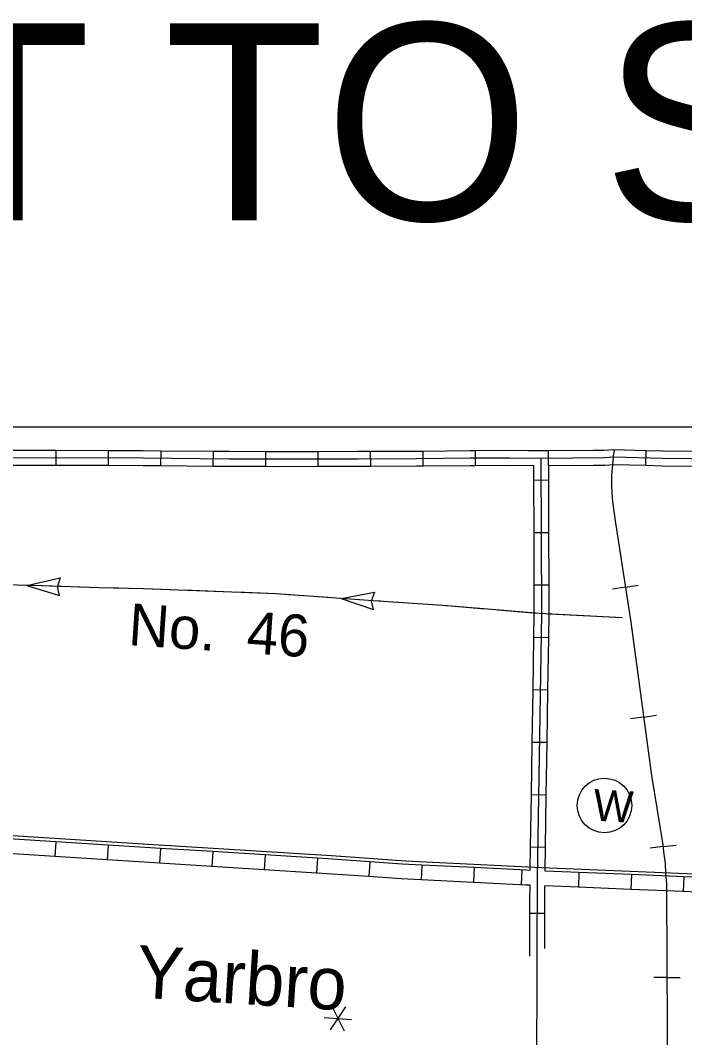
# Model space of a CAD drawing. Extents: x 1366406 to 1373462, y 376856 to 381998.
# Drawn here: x 1369100.9 to 1369209.2, y 380268.5 to 380434.5 of the extents above; entities that cross this region are included whole.
import ezdxf

# ---------------------------------------------------------------- set-up
doc = ezdxf.new("R2010")
doc.units = 0
for name, color, linetype in [('24', 7, 'Continuous'), ('32', 7, 'Continuous'), ('40', 7, 'Continuous'), ('43', 7, 'Continuous'), ('45', 7, 'Continuous'), ('48', 7, 'Continuous'), ('57', 7, 'Continuous'), ('Level 2', 7, 'Continuous'), ('R_No Plot', 7, 'Continuous')]:
    doc.layers.add(name, color=color, linetype=linetype)

msp = doc.modelspace()

# ---------------------------------------------------------------- linework, layer by layer
at = {"layer": '32'}
for p, q in [((1369106.69, 380361.9), (1369106.7, 380364.33)), ((1369115.24, 380361.87), (1369115.25, 380364.3)), ((1369123.79, 380361.83), (1369123.81, 380364.26)), ((1369132.34, 380361.75), (1369132.37, 380364.18)), ((1369140.9, 380361.71), (1369140.91, 380364.14)), ((1369149.46, 380361.71), (1369149.46, 380364.14)), ((1369158.02, 380361.73), (1369158.01, 380364.16)), ((1369166.58, 380361.77), (1369166.56, 380364.2)), ((1369175.13, 380361.86), (1369175.12, 380364.29)), ((1369187.06, 380359.43), (1369184.63, 380359.42)), ((1369187.09, 380350.87), (1369184.66, 380350.86)), ((1369187.13, 380342.32), (1369184.7, 380342.31)), ((1369187.08, 380333.74), (1369184.65, 380333.78)), ((1369186.94, 380325.19), (1369184.51, 380325.23)), ((1369186.8, 380316.64), (1369184.37, 380316.68)), ((1369186.66, 380308.08), (1369184.24, 380308.12)), ((1369106.64, 380300.47), (1369106.48, 380298.05)), ((1369115.17, 380299.93), (1369115.02, 380297.5)), ((1369123.71, 380299.39), (1369123.56, 380296.96)), ((1369132.24, 380298.85), (1369132.09, 380296.43)), ((1369186.53, 380299.53), (1369184.1, 380299.57)), ((1369140.78, 380298.32), (1369140.63, 380295.89)), ((1369149.32, 380297.78), (1369149.17, 380295.36)), ((1369157.86, 380297.2), (1369157.69, 380294.77)), ((1369166.37, 380296.67), (1369166.25, 380294.24)), ((1369174.92, 380296.25), (1369174.8, 380293.82)), ((1369182.68, 380295.86), (1369182.56, 380293.44)), ((1369191.99, 380295.46), (1369191.9, 380293.03)), ((1369200.54, 380295.11), (1369200.44, 380292.69)), ((1369209.09, 380294.76), (1369208.99, 380292.34)), ((1369186.42, 380288.76), (1369183.99, 380288.77))]:
    msp.add_line(p, q, dxfattribs=at)
for points in [[(1368944.66, 380365.32), (1368945.27, 380364.79), (1368945.98, 380364.3), (1368947.17, 380363.76), (1368948.17, 380363.56), (1368949.47, 380363.57), (1368950.6, 380363.56), (1368977.56, 380363.5), (1368994.49, 380363.45), (1369014.52, 380363.36), (1369057.49, 380363.5), (1369079.6, 380363.29), (1369099.69, 380363.13), (1369120.87, 380363.07), (1369134.89, 380362.95), (1369142.96, 380362.92), (1369155.95, 380362.94), (1369165.49, 380362.98), (1369174.24, 380363.07), (1369180.67, 380363.1), (1369185.83, 380363.06)], [(1369098.15, 380364.36), (1369099.7, 380364.35), (1369106.7, 380364.33)], [(1369106.7, 380364.33), (1369115.25, 380364.3)], [(1369115.25, 380364.3), (1369120.88, 380364.28), (1369123.81, 380364.26)], [(1369123.81, 380364.26), (1369132.37, 380364.18)], [(1369132.37, 380364.18), (1369134.9, 380364.16), (1369140.91, 380364.14)], [(1369140.91, 380364.14), (1369142.96, 380364.13), (1369149.46, 380364.14)], [(1369149.46, 380364.14), (1369155.94, 380364.16), (1369158.01, 380364.16)], [(1369158.01, 380364.16), (1369165.48, 380364.19), (1369166.56, 380364.2)], [(1369166.56, 380364.2), (1369174.23, 380364.28), (1369175.12, 380364.29)], [(1369175.12, 380364.29), (1369180.67, 380364.32), (1369183.68, 380364.29)], [(1369183.68, 380364.29), (1369187.04, 380364.27)], [(1369187.06, 380359.43), (1369187.04, 380364.27)], [(1369098.13, 380361.93), (1369099.69, 380361.92), (1369106.69, 380361.9)], [(1369106.69, 380361.9), (1369115.24, 380361.87)], [(1369115.24, 380361.87), (1369120.86, 380361.85), (1369123.79, 380361.83)], [(1369123.79, 380361.83), (1369132.34, 380361.75)], [(1369132.34, 380361.75), (1369134.88, 380361.73), (1369140.9, 380361.71)], [(1369158.02, 380361.73), (1369165.5, 380361.76), (1369166.58, 380361.77)], [(1369166.58, 380361.77), (1369174.25, 380361.85), (1369175.13, 380361.86)], [(1369175.13, 380361.86), (1369180.67, 380361.89), (1369184.62, 380361.86)], [(1369184.63, 380359.42), (1369184.62, 380361.86)], [(1369185.19, 380282.45), (1369185.23, 380294.52), (1369185.93, 380337.65), (1369185.83, 380363.06)], [(1369140.9, 380361.71), (1369142.96, 380361.7), (1369149.46, 380361.71)], [(1369149.46, 380361.71), (1369155.95, 380361.73), (1369158.02, 380361.73)], [(1369184.66, 380350.86), (1369184.63, 380359.42)], [(1369187.09, 380350.87), (1369187.06, 380359.43)], [(1369184.7, 380342.31), (1369184.66, 380350.86)], [(1369187.13, 380342.32), (1369187.09, 380350.87)], [(1369184.65, 380333.78), (1369184.71, 380337.66), (1369184.7, 380342.31)], [(1369187.08, 380333.74), (1369187.14, 380337.65), (1369187.13, 380342.32)], [(1369184.51, 380325.23), (1369184.65, 380333.78)], [(1369186.94, 380325.19), (1369187.08, 380333.74)], [(1369184.37, 380316.68), (1369184.51, 380325.23)], [(1369186.8, 380316.64), (1369186.94, 380325.19)], [(1369184.24, 380308.12), (1369184.37, 380316.68)], [(1369186.66, 380308.08), (1369186.8, 380316.64)], [(1369184.1, 380299.57), (1369184.24, 380308.12)], [(1369186.53, 380299.53), (1369186.66, 380308.08)], [(1369252.4, 380293.26), (1369251.01, 380293.38), (1369242.85, 380293.7), (1369229.28, 380294.44), (1369185.88, 380296.21), (1369163.73, 380297.31), (1369151.6, 380298.16), (1369120.91, 380300.08), (1369100.42, 380301.39), (1369085.32, 380302.07), (1369046.26, 380303.51), (1369036.14, 380303.8), (1369035.29, 380303.84)], [(1369106.64, 380300.47), (1369099.84, 380300.91), (1369098.08, 380300.99)], [(1369115.17, 380299.93), (1369106.64, 380300.47)], [(1369123.71, 380299.39), (1369120.34, 380299.6), (1369115.17, 380299.93)], [(1369132.24, 380298.85), (1369123.71, 380299.39)], [(1369140.78, 380298.32), (1369132.24, 380298.85)], [(1369184.04, 380295.8), (1369184.1, 380299.57)], [(1369186.46, 380295.69), (1369186.53, 380299.53)], [(1369106.48, 380298.05), (1369099.71, 380298.48), (1369097.97, 380298.56)], [(1369115.02, 380297.5), (1369106.48, 380298.05)], [(1369123.56, 380296.96), (1369120.18, 380297.18), (1369115.02, 380297.5)], [(1369149.32, 380297.78), (1369140.78, 380298.32)], [(1369157.86, 380297.2), (1369151.04, 380297.68), (1369149.32, 380297.78)], [(1369166.37, 380296.67), (1369163.15, 380296.83), (1369157.86, 380297.2)], [(1369132.09, 380296.43), (1369123.56, 380296.96)], [(1369140.63, 380295.89), (1369132.09, 380296.43)], [(1369149.17, 380295.36), (1369140.63, 380295.89)], [(1369174.92, 380296.25), (1369166.37, 380296.67)], [(1369183.46, 380295.83), (1369174.92, 380296.25)], [(1369184.04, 380295.8), (1369183.46, 380295.83)], [(1369191.99, 380295.46), (1369186.46, 380295.69)], [(1369200.54, 380295.11), (1369191.99, 380295.46)], [(1369157.69, 380294.77), (1369150.88, 380295.25), (1369149.17, 380295.36)], [(1369166.25, 380294.24), (1369163.01, 380294.4), (1369157.69, 380294.77)], [(1369174.8, 380293.82), (1369166.25, 380294.24)], [(1369183.34, 380293.4), (1369174.8, 380293.82)], [(1369209.09, 380294.76), (1369200.54, 380295.11)], [(1369217.63, 380294.42), (1369209.09, 380294.76)], [(1369184.01, 380293.37), (1369183.34, 380293.4)], [(1369184, 380291), (1369184.01, 380293.37)], [(1369186.43, 380290.99), (1369186.44, 380293.26)], [(1369191.9, 380293.03), (1369186.44, 380293.26)], [(1369200.44, 380292.69), (1369191.9, 380293.03)], [(1369208.99, 380292.34), (1369200.44, 380292.69)], [(1369217.53, 380291.99), (1369208.99, 380292.34)], [(1369183.97, 380281.79), (1369184, 380291)], [(1369186.41, 380283.05), (1369186.43, 380290.99)], [(1369185.11, 380260.71), (1369185.19, 380282.45)]]:
    msp.add_lwpolyline(points, dxfattribs=at)
at = {"layer": '40'}
for p, q in [((1369199.57, 380341.99), (1369197.46, 380341.66)), ((1369199.57, 380341.99), (1369201.68, 380342.32)), ((1369202.53, 380320.81), (1369200.41, 380320.53)), ((1369202.53, 380320.81), (1369204.65, 380321.1)), ((1369205.71, 380299.67), (1369203.59, 380299.42)), ((1369205.71, 380299.67), (1369207.83, 380299.92)), ((1369206.36, 380278.31), (1369204.22, 380278.31)), ((1369206.36, 380278.31), (1369208.5, 380278.32))]:
    msp.add_line(p, q, dxfattribs=at)
for points in [[(1369197.59, 380363.2), (1369197.84, 380364.44)], [(1369197.59, 380363.2), (1369197.28, 380360.23), (1369197.29, 380358.4), (1369197.41, 380356.64), (1369197.49, 380355.96), (1369197.89, 380352.83), (1369200.46, 380336.27), (1369203.81, 380311.28), (1369205.68, 380299.96), (1369205.85, 380298.46), (1369206.05, 380296.91), (1369206.13, 380295.33), (1369206.26, 380293.62), (1369206.25, 380292.3), (1369206.35, 380281.46), (1369206.39, 380269.7), (1369206.62, 380250.35)]]:
    msp.add_lwpolyline(points, dxfattribs=at)
at = {"layer": '43'}
for p, q in [((1369101.92, 380342.28), (1369107.34, 380343.54)), ((1369107.34, 380343.54), (1369106.91, 380342.12)), ((1369101.92, 380342.28), (1369107.24, 380340.66)), ((1369107.24, 380340.66), (1369106.91, 380342.11)), ((1369153.19, 380340.16), (1369158.65, 380341.2)), ((1369158.65, 380341.2), (1369158.17, 380339.8)), ((1369153.19, 380340.16), (1369158.45, 380338.33)), ((1369158.45, 380338.33), (1369158.17, 380339.79))]:
    msp.add_line(p, q, dxfattribs=at)
for points in [[(1369199.06, 380336.99), (1369185.55, 380337.68), (1369170.56, 380338.94), (1369158.41, 380339.78), (1369142.58, 380340.92), (1369120.88, 380341.72), (1369113.65, 380341.9), (1369102.97, 380342.24), (1369089.81, 380342.55), (1369078.65, 380343.02), (1369057.37, 380343.94), (1369039.23, 380345), (1369023.55, 380345.34), (1369019.15, 380345.43)], [(1369108.34, 380342.07), (1369102.97, 380342.24), (1369101.92, 380342.27)], [(1369116.89, 380341.82), (1369113.65, 380341.9), (1369110.47, 380342)], [(1369125.43, 380341.56), (1369120.88, 380341.72), (1369119.02, 380341.77)], [(1369133.98, 380341.24), (1369127.57, 380341.48)], [(1369142.53, 380340.92), (1369136.12, 380341.16)], [(1369147.86, 380340.54), (1369144.66, 380340.77)], [(1369151.06, 380340.31), (1369147.86, 380340.54)], [(1369159.59, 380339.7), (1369158.41, 380339.78), (1369153.19, 380340.16)], [(1369168.13, 380339.11), (1369161.73, 380339.55)], [(1369176.65, 380338.43), (1369170.56, 380338.94), (1369170.26, 380338.96)], [(1369185.18, 380337.71), (1369178.78, 380338.25)], [(1369193.72, 380337.26), (1369187.31, 380337.59)], [(1369199.06, 380336.99), (1369195.85, 380337.15)]]:
    msp.add_lwpolyline(points, dxfattribs=at)
at = {"layer": '45'}
msp.add_line((1369202.9, 380361.87), (1369202.97, 380364.3), dxfattribs=at)
for points in [[(1369185.83, 380363.06), (1369196.17, 380363.12), (1369197.67, 380363.23), (1369205.66, 380363.01), (1369219.62, 380362.89), (1369224.35, 380362.87), (1369226.34, 380362.87), (1369234.37, 380363.49), (1369235.08, 380363.4), (1369235.75, 380362.73)], [(1369187.04, 380364.27), (1369194.38, 380364.33)], [(1369194.38, 380364.33), (1369196.13, 380364.34), (1369197.64, 380364.45), (1369202.97, 380364.3)], [(1369202.97, 380364.3), (1369205.68, 380364.22), (1369211.49, 380364.18)], [(1369187.05, 380361.86), (1369194.39, 380361.9)], [(1369194.39, 380361.9), (1369196.22, 380361.91), (1369197.7, 380362.01), (1369202.9, 380361.87)], [(1369202.9, 380361.87), (1369205.64, 380361.79), (1369211.47, 380361.75)]]:
    msp.add_lwpolyline(points, dxfattribs=at)
at = {"layer": '48'}
for p, q in [((1369153.91, 380273.51), (1369151.42, 380269.76)), ((1369151.66, 380273.65), (1369153.66, 380269.62)), ((1369150.42, 380271.77), (1369154.91, 380271.49))]:
    msp.add_line(p, q, dxfattribs=at)
at = {"layer": '57'}
msp.add_circle((1369196.16, 380306.39), 4.45, dxfattribs=at)
at = {"layer": 'R_No Plot'}
msp.add_line((1368990.63, 380368.17), (1369713.09, 380368.17), dxfattribs=at)

# ---------------------------------------------------------------- texts
at = {"layer": '24'}
msp.add_text('Yarbro', height=8.554, rotation=356.4139, dxfattribs=at).set_placement((1369119.58, 380275.08))
at = {"layer": '43'}
msp.add_text('No.  46', height=6.843, rotation=356.1113, dxfattribs=at).set_placement((1369118.35, 380332.55))
at = {"layer": '57'}
msp.add_text('W', height=5.13, rotation=356.4139, dxfattribs=at).set_placement((1369194.2, 380303.94))
at = {"layer": 'Level 2'}
msp.add_text('NOT TO SCALE', height=32.1288, dxfattribs=at).set_placement((1369021.66, 380401.85))

doc.saveas('drawing.dxf')
